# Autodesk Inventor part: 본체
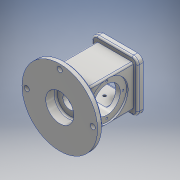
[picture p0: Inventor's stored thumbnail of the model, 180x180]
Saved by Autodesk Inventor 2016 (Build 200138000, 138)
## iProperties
Created: 2019-08
Part Number: 본체
Material: 알루미늄 6061
Document SubType Name: Modeling
Designer: 3sil_0101
Density: 2.7 g/cm^3
Appearance: 알루미늄 - 평지
Mass: 1016.75 g
Surface Area: 790.795 cm^2
Volume: 376.574 cm^3
Author: 3sil_0101
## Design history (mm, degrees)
sketch "스케치1"
  geometry: L1 (33, 37)-(-33, 37); L2 (-33, 37)-(-33, -37); L3 (-33, -37)-(33, -37); L4 (33, -37)-(33, 37); 2 further points
  constraints: 8 end point, 2 midpoint, 2 parallel, 1 horizontal, 1 perpendicular
  dimensions: "d0" = 74 distance of L3.end L1.start; "d1" = 66 distance of L2.end L3.end
extrude "돌출1" new body sketch "스케치1" stored distance "d4" = 88; taper "d5" = 0 deg
sketch "스케치7"
  geometry: L1 (-22, -22)-(22, -22); L2 (22, -22)-(22, 22); L3 (22, 22)-(-22, 22); L4 (-22, 22)-(-22, -22); 3 further points
  constraints: 8 end point, 2 midpoint, 2 parallel, 1 horizontal, 1 horizontal alignment, 1 perpendicular, 1 vertical alignment
  dimensions: "d44" = 44 distance of L3.end L2.end; "d45" = 44 distance of L2.end L1.end
extrude "돌출7" cut sketch "스케치7" distance "d48" = 72; taper "d49" = 0 deg
sketch "스케치2"
  geometry: C1 r 67.5 at (0, 0); C2 r 4.5 at (-59, 0); C3 r 4.5 at (0, 59); C4 r 4.5 at (59, 0); 1 further point
  constraints: 4 centre point, 1 coincident, 1 equal radius, 1 horizontal alignment
  dimensions: "d6" = 135 diameter of C1; "d7" = 9 diameter of C2; "d8" = 118 distance of C4.centre C2.centre; "d9" = 59 distance of point (0, 0) C2.centre; "d10" = 59 distance of point (0, 0) C3.centre
extrude "돌출2" join sketch "스케치2" distance "d12" = 10; taper "d13" = 0 deg
sketch "스케치3"
  geometry: L1 (-41, -46)-(41, -46); L2 (41, -46)-(41, 46); L3 (41, 46)-(-41, 46); L4 (-41, 46)-(-41, -46); L5 (-22, 22)-(-22, -22) reference; L6 (-22, -22)-(22, -22) reference; L7 (22, -22)-(22, 22) reference; L8 (22, 22)-(-22, 22) reference; L9 (-27.5, -27.5)-(27.5, -27.5); L10 (27.5, -27.5)-(27.5, 27.5); L11 (27.5, 27.5)-(-27.5, 27.5); L12 (-27.5, 27.5)-(-27.5, -27.5); 4 further points
  constraints: 16 end point, 4 midpoint, 4 parallel, 2 horizontal, 2 perpendicular, 1 horizontal alignment, 1 vertical alignment
  dimensions: "d14" = 92 distance of L3.end L1.start; "d15" = 82 distance of L2.end L3.end; "d20" = 55 distance of L11.end L10.end; "d21" = 55 distance of L10.end L9.end
extrude "돌출3" join sketch "스케치3" distance "d16" = 10; taper "d17" = 0 deg
fillet "모깎기1" dims "d18" = 10
fillet "모깎기2" dims "d19" = 3
sketch "스케치4"
  geometry: L1 (-33.5, -13)-(101.5, -13) reference; C1 r 24 at (34, 41); 1 further point
  constraints: 1 centre point
  dimensions: "d22" = 54 distance from line of C1.centre L1; "d23" = 48 diameter of C1
extrude "돌출4" cut sketch "스케치4" distance "d24" = 78; taper "d25" = 0 deg
sketch "스케치5"
  geometry: C1 r 35 at (34, 41); 1 further point
  constraints: 1 centre point, 1 coincident
  dimensions: "d26" = 70 diameter of C1
extrude "돌출5" cut sketch "스케치5" distance "d27" = 3; taper "d28" = 0 deg
sketch "스케치6"
  geometry: C1 r 35 at (-34, 41); 1 further point
  constraints: 1 centre point, 1 coincident
  dimensions: "d29" = 70 diameter of C1
extrude "돌출6" cut sketch "스케치6" distance "d30" = 3; taper "d31" = 0 deg
chamfer "모따기1" distance "d32" = 3; stored, may be unused: second distance "d33" = 2, angle "d34" = 45 deg
hole "구멍1" diameter "d37" = 25; stored, may be unused: countersink angle "d41" = 90 deg, drill point angle "d43" = 118 deg; dims "d38" = 6, "d39" = 50, "d40" = 18, "d42" = 8, "d46" = 10, "d47" = 10
fillet "모깎기3" dims "d50" = 3
sketch "스케치8"
  geometry: 1 further point
sketch "스케치9"
  geometry: 2 further points
  constraints: 1 vertical alignment
  dimensions: "d51" = 29 distance of point (0, 0) point (0, 29)
hole "구멍2" sketch "스케치9" at (0, 29) diameter "d52" = 3.242; stored, may be unused: countersink angle "d56" = 90 deg, drill point angle "d58" = 118 deg; dims "d53" = 4, "d54" = 50, "d55" = 18, "d57" = 6
sketch "스케치10"
  geometry: L1 (-41, 36)-(-41, -36) reference; L2 (-31, -46)-(31, -46) reference; 2 further points
  dimensions: "d62" = 10 distance from line of point (-31, -36) L1; "d63" = 10 distance from line of L2 point (-31, -36)
hole "구멍3" sketch "스케치10" at (-31, -36) diameter "d64" = 3.242; stored, may be unused: countersink angle "d68" = 90 deg, drill point angle "d70" = 118 deg; dims "d65" = 4, "d66" = 50, "d67" = 18, "d69" = 6
chamfer "모따기2" distance "d77" = 1; stored, may be unused: second distance "d78" = 2, angle "d79" = 45 deg
fillet "모깎기4" dims "d80" = 3
sketch "스케치11"
  geometry: C1 r 4.5 at (-59, 0) reference; 2 further points
  constraints: 1 coincident, 1 horizontal alignment, 2 other
sketch "스케치12"
  geometry: L1 (-37.5, -98)-(97.5, -98) reference; 3 further points
  constraints: 2 vertical alignment
  dimensions: "d82" = 43 distance of point (30, -61) point (30, -18); "d83" = 37 distance from line of L1 point (30, -61)
hole "구멍4" sketch "스케치12" at (30, -18), (30, -61) diameter "d84" = 4.917; stored, may be unused: countersink angle "d88" = 90 deg, drill point angle "d90" = 118 deg; dims "d85" = 27, "d86" = 50, "d87" = 18, "d89" = 32.1
feature "엠보싱1" dims "d0" = 74, "d1" = 66, "d91" = 0.5, "d92" = 0
sketch "스케치13"
  geometry: L1 (-27.5, 27.5)-(-27.5, -27.5) reference; L2 (-27.5, -27.5)-(27.5, -27.5) reference; L3 (27.5, -27.5)-(27.5, 27.5) reference; L4 (27.5, 27.5)-(-27.5, 27.5) reference; L5 (22, 19)-(22, -19) reference; L6 (19, -22)-(-19, -22) reference; L7 (-22, -19)-(-22, 19) reference; L8 (-19, 22)-(19, 22) reference; A1 r 3 centre (19, -19) between (19, -22) and (22, -19) reference; A2 r 3 centre (-19, -19) between (-22, -19) and (-19, -22) reference; A3 r 3 centre (-19, 19) between (-19, 22) and (-22, 19) reference; A4 r 3 centre (19, 19) between (22, 19) and (19, 22) reference; 1 further point
extrude "돌출8" join sketch "스케치13" distance "d93" = 2; taper "d94" = 0 deg
node "솔리드1"
pattern_circular "원형 패턴1" dims angle "d60" = 360 deg
mirror "대칭1"
pattern_linear "직사각형 패턴1" dims "d73" = 72, "d76" = 62
node "투영된 루프1"
node "투영된 루프2"
